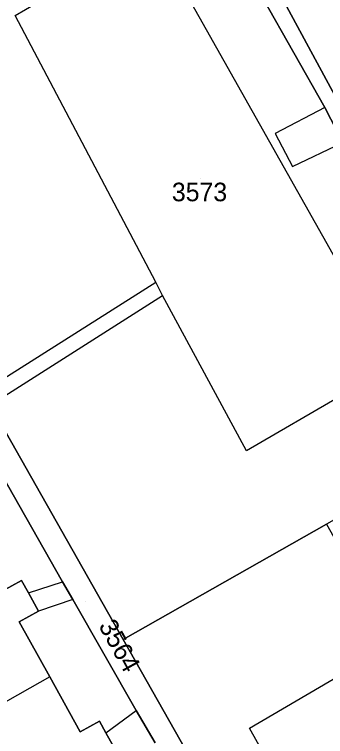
# Model space of a CAD drawing. Extents: x -262715 to -259381, y -1237238 to -1231182.
# Drawn here: x -261574 to -261540.5, y -1235944.8 to -1235867.1 of the extents above; entities that cross this region are included whole.
import ezdxf

# ---------------------------------------------------------------- set-up
doc = ezdxf.new("R2010")
doc.units = 0
for name, color, linetype in [('body_kn', 7, 'Continuous'), ('kladpar_druhypozemkov', 7, 'Continuous'), ('kladpar_hranice', 7, 'Continuous'), ('kladpar_parcelnecisla', 7, 'Continuous'), ('kladpar_plochy', 7, 'Continuous'), ('zappar_hrandruhpozemk', 7, 'Continuous')]:
    doc.layers.add(name, color=color, linetype=linetype)

msp = doc.modelspace()

# ---------------------------------------------------------------- linework, layer by layer
at = {"layer": 'body_kn'}
for p, q in [((-261573.97, -1235867.17), (-261573.97, -1235867.17)), ((-261540.64, -1235877.08), (-261540.64, -1235877.08)), ((-261540.64, -1235877.08), (-261540.64, -1235877.08)), ((-261545.96, -1235879.88), (-261545.96, -1235879.88)), ((-261544.1, -1235883.45), (-261544.1, -1235883.45)), ((-261558.81, -1235895.91), (-261558.81, -1235895.91)), ((-261558.09, -1235897.35), (-261558.09, -1235897.35)), ((-261549.05, -1235914.08), (-261549.05, -1235914.08)), ((-261573.29, -1235928.02), (-261573.29, -1235928.02)), ((-261568.88, -1235928.18), (-261568.88, -1235928.18)), ((-261572.54, -1235929.37), (-261572.54, -1235929.37)), ((-261572.54, -1235929.37), (-261572.54, -1235929.37)), ((-261567.77, -1235930.08), (-261567.77, -1235930.08)), ((-261567.77, -1235930.08), (-261567.77, -1235930.08)), ((-261571.45, -1235931.34), (-261571.45, -1235931.34)), ((-261573.52, -1235932.49), (-261573.52, -1235932.49)), ((-261562.34, -1235934.38), (-261562.34, -1235934.38)), ((-261570.24, -1235938.41), (-261570.24, -1235938.41)), ((-261570.24, -1235938.41), (-261570.24, -1235938.41)), ((-261560.94, -1235942.05), (-261560.94, -1235942.05)), ((-261564.88, -1235943.2), (-261564.88, -1235943.2)), ((-261548.74, -1235943.95), (-261548.74, -1235943.95)), ((-261566.95, -1235944.34), (-261566.95, -1235944.34)), ((-261564.19, -1235944.45), (-261564.19, -1235944.45)), ((-261564.19, -1235944.45), (-261564.19, -1235944.45))]:
    msp.add_line(p, q, dxfattribs=at)
at = {"layer": 'kladpar_druhypozemkov'}
for p, q in [((-261554.03, -1235884.78), (-261554.03, -1235884.78)), ((-261566.38, -1235930.34), (-261566.38, -1235930.34))]:
    msp.add_line(p, q, dxfattribs=at)
at = {"layer": 'kladpar_hranice'}
for points in [[(-261561.64, -1235840.09), (-261553.29, -1235855.08), (-261550.64, -1235859.41), (-261540.64, -1235877.08), (-261538.69, -1235880.86), (-261525.12, -1235904.42), (-261524.09, -1235906.23), (-261522.2, -1235909.63), (-261522.2, -1235910.88), (-261522.89, -1235911.99), (-261540.46, -1235921.96), (-261562.34, -1235934.38), (-261576.65, -1235909.14), (-261577.52, -1235907.74), (-261598.05, -1235872.26), (-261592.46, -1235857.37), (-261566.2, -1235842.67), (-261561.64, -1235840.09)], [(-261544.98, -1235865.77), (-261538.62, -1235877.52), (-261536.85, -1235880.56), (-261533.11, -1235887.24), (-261530.97, -1235890.86), (-261524.24, -1235902.92), (-261522.33, -1235906.3), (-261521.31, -1235907.77), (-261520.15, -1235908.45), (-261518.35, -1235908.32), (-261522.89, -1235911.99), (-261522.2, -1235910.88), (-261522.2, -1235909.63), (-261524.09, -1235906.23), (-261525.12, -1235904.42), (-261538.69, -1235880.86), (-261540.64, -1235877.08), (-261550.64, -1235859.41)], [(-261534.38, -1235866.93), (-261530.5, -1235873.86), (-261529.53, -1235875.61), (-261527.23, -1235879.71), (-261524.88, -1235883.91), (-261523.76, -1235885.92), (-261520.08, -1235892.5), (-261516.2, -1235899.43), (-261515.22, -1235901.18), (-261512.92, -1235905.29), (-261518.35, -1235908.32), (-261520.15, -1235908.45), (-261521.31, -1235907.77), (-261522.33, -1235906.3), (-261524.24, -1235902.92), (-261530.97, -1235890.86), (-261533.11, -1235887.24), (-261536.85, -1235880.56), (-261538.62, -1235877.52), (-261544.98, -1235865.77)], [(-261576.65, -1235909.14), (-261562.34, -1235934.38), (-261541.17, -1235971.75), (-261540.25, -1235973.27), (-261523.55, -1236004.88), (-261522.88, -1236005.56), (-261522.13, -1236005.25), (-261501.2, -1235993.19), (-261500.8, -1235992.47), (-261499.36, -1235989.85), (-261496.11, -1235987.16), (-261494.56, -1235986.29), (-261494.01, -1235986.84), (-261492.38, -1235990)], [(-261558.9, -1235945.51), (-261560.94, -1235942.05), (-261567.77, -1235930.08), (-261568.88, -1235928.18), (-261576.8, -1235914.26)], [(-261576.8, -1235914.26), (-261568.88, -1235928.18), (-261567.77, -1235930.08), (-261560.94, -1235942.05), (-261558.9, -1235945.51)], [(-261540.46, -1235921.96), (-261527.77, -1235944.43), (-261522.17, -1235954.47), (-261521.38, -1235955.88), (-261520.63, -1235957.14), (-261519.51, -1235959.03), (-261505.56, -1235983.78), (-261504.77, -1235985.18), (-261500.84, -1235992.1), (-261500.8, -1235992.47), (-261500.77, -1235992.79), (-261501.2, -1235993.19), (-261522.13, -1236005.25), (-261522.88, -1236005.56), (-261523.55, -1236004.88), (-261540.25, -1235973.27), (-261541.17, -1235971.75), (-261562.34, -1235934.38), (-261540.46, -1235921.96)], [(-261575.36, -1235929.17), (-261573.29, -1235928.02), (-261572.54, -1235929.37), (-261571.45, -1235931.34), (-261573.52, -1235932.49), (-261570.24, -1235938.41), (-261566.95, -1235944.34), (-261564.88, -1235943.2), (-261564.19, -1235944.45), (-261563.06, -1235946.49), (-261565.12, -1235947.64), (-261561.83, -1235953.58), (-261558.54, -1235959.51), (-261556.47, -1235958.36), (-261555.74, -1235959.67), (-261554.66, -1235961.62), (-261556.73, -1235962.77), (-261552.85, -1235969.76), (-261553.86, -1235970.39), (-261563.9, -1235975.4), (-261567.24, -1235969.44), (-261568.32, -1235967.51), (-261572.62, -1235959.85), (-261575.78, -1235954.2)], [(-261563.06, -1235946.49), (-261564.19, -1235944.45), (-261564.88, -1235943.2), (-261566.95, -1235944.34), (-261570.24, -1235938.41), (-261573.52, -1235932.49), (-261571.45, -1235931.34), (-261572.54, -1235929.37), (-261573.29, -1235928.02), (-261575.36, -1235929.17)]]:
    msp.add_lwpolyline(points, dxfattribs=at)
at = {"layer": 'kladpar_plochy'}
for points in [[(-261561.64, -1235840.09), (-261553.29, -1235855.08), (-261550.64, -1235859.41), (-261540.64, -1235877.08), (-261538.69, -1235880.86), (-261525.12, -1235904.42), (-261524.09, -1235906.23), (-261522.2, -1235909.63), (-261522.2, -1235910.88), (-261522.89, -1235911.99), (-261540.46, -1235921.96), (-261562.34, -1235934.38), (-261576.65, -1235909.14), (-261577.52, -1235907.74), (-261598.05, -1235872.26), (-261592.46, -1235857.37), (-261566.2, -1235842.67)], [(-261540.46, -1235921.96), (-261527.77, -1235944.43), (-261522.17, -1235954.47), (-261521.38, -1235955.88), (-261520.63, -1235957.14), (-261519.51, -1235959.03), (-261505.56, -1235983.78), (-261504.77, -1235985.18), (-261500.84, -1235992.1), (-261500.8, -1235992.47), (-261500.77, -1235992.79), (-261501.2, -1235993.19), (-261522.13, -1236005.25), (-261522.88, -1236005.56), (-261523.55, -1236004.88), (-261540.25, -1235973.27), (-261541.17, -1235971.75), (-261562.34, -1235934.38)]]:
    msp.add_lwpolyline(points, close=True, dxfattribs=at)
for points in [[(-261544.98, -1235865.77), (-261538.62, -1235877.52), (-261536.85, -1235880.56), (-261533.11, -1235887.24), (-261530.97, -1235890.86), (-261524.24, -1235902.92), (-261522.33, -1235906.3), (-261521.31, -1235907.77), (-261520.15, -1235908.45), (-261518.35, -1235908.32), (-261522.89, -1235911.99), (-261522.2, -1235910.88), (-261522.2, -1235909.63), (-261524.09, -1235906.23), (-261525.12, -1235904.42), (-261538.69, -1235880.86), (-261540.64, -1235877.08), (-261550.64, -1235859.41)], [(-261534.38, -1235866.93), (-261530.5, -1235873.86), (-261529.53, -1235875.61), (-261527.23, -1235879.71), (-261524.88, -1235883.91), (-261523.76, -1235885.92), (-261520.08, -1235892.5), (-261516.2, -1235899.43), (-261515.22, -1235901.18), (-261512.92, -1235905.29), (-261518.35, -1235908.32), (-261520.15, -1235908.45), (-261521.31, -1235907.77), (-261522.33, -1235906.3), (-261524.24, -1235902.92), (-261530.97, -1235890.86), (-261533.11, -1235887.24), (-261536.85, -1235880.56), (-261538.62, -1235877.52), (-261544.98, -1235865.77)], [(-261576.65, -1235909.14), (-261562.34, -1235934.38), (-261541.17, -1235971.75)], [(-261558.9, -1235945.51), (-261560.94, -1235942.05), (-261567.77, -1235930.08), (-261568.88, -1235928.18), (-261576.8, -1235914.26)], [(-261576.8, -1235914.26), (-261568.88, -1235928.18), (-261567.77, -1235930.08), (-261560.94, -1235942.05), (-261558.9, -1235945.51)], [(-261575.36, -1235929.17), (-261573.29, -1235928.02), (-261572.54, -1235929.37), (-261571.45, -1235931.34), (-261573.52, -1235932.49), (-261570.24, -1235938.41), (-261566.95, -1235944.34), (-261564.88, -1235943.2), (-261564.19, -1235944.45), (-261563.06, -1235946.49), (-261565.12, -1235947.64), (-261561.83, -1235953.58), (-261558.54, -1235959.51), (-261556.47, -1235958.36), (-261555.74, -1235959.67), (-261554.66, -1235961.62), (-261556.73, -1235962.77), (-261552.85, -1235969.76), (-261553.86, -1235970.39), (-261563.9, -1235975.4), (-261567.24, -1235969.44), (-261568.32, -1235967.51), (-261572.62, -1235959.85), (-261575.78, -1235954.2)], [(-261563.06, -1235946.49), (-261564.19, -1235944.45), (-261564.88, -1235943.2), (-261566.95, -1235944.34), (-261570.24, -1235938.41), (-261573.52, -1235932.49), (-261571.45, -1235931.34), (-261572.54, -1235929.37), (-261573.29, -1235928.02), (-261575.36, -1235929.17)]]:
    msp.add_lwpolyline(points, dxfattribs=at)
at = {"layer": 'zappar_hrandruhpozemk'}
for p, q in [((-261573.97, -1235867.17), (-261559.12, -1235858.54)), ((-261540.64, -1235877.08), (-261545.96, -1235879.88)), ((-261577.52, -1235907.74), (-261558.81, -1235895.91)), ((-261576.65, -1235909.14), (-261558.09, -1235897.35)), ((-261533.12, -1235904.76), (-261549.05, -1235914.08)), ((-261572.54, -1235929.37), (-261568.88, -1235928.18)), ((-261567.77, -1235930.08), (-261571.45, -1235931.34)), ((-261548.74, -1235943.95), (-261535.67, -1235936.25)), ((-261570.24, -1235938.41), (-261581.16, -1235944.62)), ((-261564.19, -1235944.45), (-261560.94, -1235942.05)), ((-261536.75, -1235965.11), (-261548.74, -1235943.95))]:
    msp.add_line(p, q, dxfattribs=at)
for points in [[(-261559.12, -1235858.54), (-261534.07, -1235903), (-261533.12, -1235904.76)], [(-261549.05, -1235914.08), (-261558.09, -1235897.35), (-261558.81, -1235895.91), (-261573.97, -1235867.17)], [(-261545.96, -1235879.88), (-261544.1, -1235883.45), (-261538.69, -1235880.86)]]:
    msp.add_lwpolyline(points, dxfattribs=at)

# ---------------------------------------------------------------- texts
at = {"layer": 'kladpar_parcelnecisla'}
msp.add_text('3573', height=2, dxfattribs=at).set_placement((-261557.093, -1235887.19))
msp.add_text('3564', height=2, rotation=299, dxfattribs=at).set_placement((-261565.029, -1235932.907))

doc.saveas('drawing.dxf')
